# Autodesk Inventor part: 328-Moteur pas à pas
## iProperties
Author: Philippe
Shininess: 20.0
Angle Display Precision: 2
Document Length Units: 11269
Document Angle Units: 11283
Document Time Units: 11279
Document Mass Units: 11290
Document Length Units Precision: 3
Document Angle Units Precision: 2
Compacted: False
PropertySet Name: _Private Model Information
Created: 2001-12
Part Number: 328-Moteur pas à pas
Material: Par défaut
Document SubType Name: Modélisation
Designer: Philippe
Control State: 0
Master: False
Checked Out: False
PropertySet Name: Design Tracking Control
Density: 0.0
Volumn: 0.0
Area: 0.0
PropertySet Name: Model Information
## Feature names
1. Extrusion1
2. Chanfrein1 [Chamfer]
3. Extrusion2
4. Chanfrein2 [Chamfer]
5. Extrusion3
6. Extrusion4
7. Extrusion5
8. Extrusion6
9. Extrusion8
10. Perçage2 [Hole]
11. Chanfrein4 [Chamfer]
12. Réseau circulaire3 [Circular Pattern]
